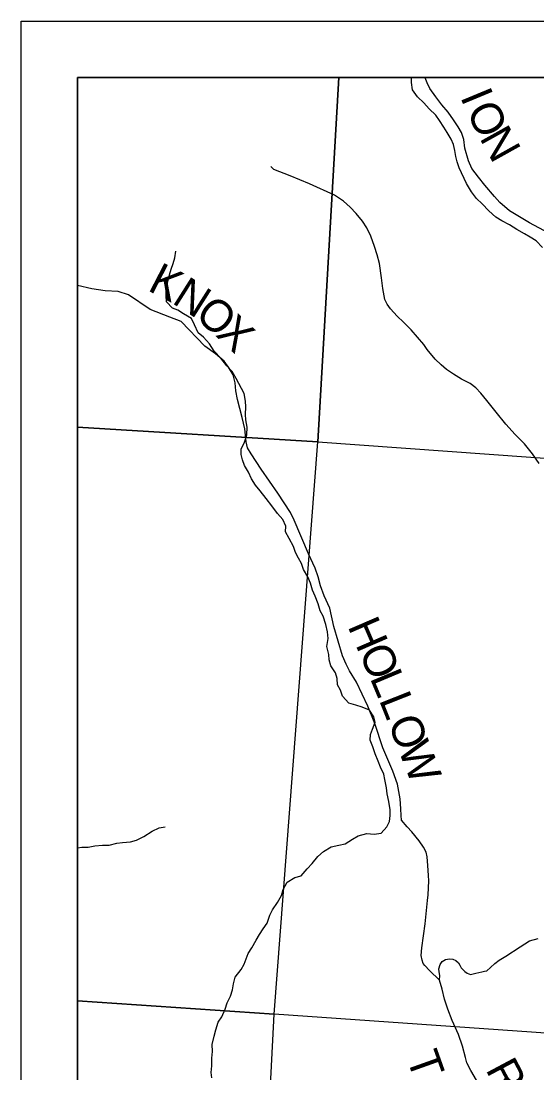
# Model space of a CAD drawing. Extents: x -13.7 to 34, y 0 to 32.3.
# Drawn here: x 23.417 to 24.332, y 19.134 to 21 of the extents above; entities that cross this region are included whole.
import ezdxf

# ---------------------------------------------------------------- set-up
doc = ezdxf.new("R2010")
doc.units = 0
for name, color, linetype in [('GM_X_Corporation', 7, 'Continuous'), ('GM_X_County_Road', 7, 'Continuous'), ('GM_X_County_Road_Text', 7, 'Continuous'), ('GM_X_Minor_River', 7, 'Continuous'), ('GM_X_Township_Road', 7, 'Continuous'), ('GM_X_Township_Road_Text', 7, 'Continuous'), ('SH_Data', 7, 'Continuous')]:
    doc.layers.add(name, color=color, linetype=linetype)

msp = doc.modelspace()

# ---------------------------------------------------------------- linework, layer by layer
at = {"layer": 'GM_X_Corporation'}
for points in [[(26.0026, 20.9), (23.5167, 20.9), (23.5167, 14.1)], [(26.0026, 20.9), (23.5167, 20.9), (23.5167, 15.1495)]]:
    msp.add_lwpolyline(points, dxfattribs=at)
for points in [[(23.9809, 20.9), (23.5167, 20.9), (23.5167, 20.2798), (23.9438, 20.2537)], [(24.9905, 20.9), (23.9809, 20.9), (23.9438, 20.2537), (24.938, 20.1823)], [(23.5167, 20.2798), (23.5167, 19.2621), (23.8661, 19.2385), (23.9438, 20.2537)], [(23.9438, 20.2537), (24.938, 20.1823), (24.8727, 19.1684), (23.8661, 19.2385)], [(23.5167, 19.2621), (23.5167, 18.2375), (23.8099, 18.2197), (23.8254, 18.4657), (23.8456, 18.8482), (23.8661, 19.2385)]]:
    msp.add_lwpolyline(points, close=True, dxfattribs=at)
at = {"layer": 'GM_X_County_Road'}
msp.add_lwpolyline([(24.3534, 20.6236), (24.3191, 20.642), (24.2838, 20.6633), (24.2666, 20.678), (24.257, 20.6889), (24.2399, 20.709), (24.2284, 20.7232), (24.217, 20.7383), (24.211, 20.7519), (24.2046, 20.7746), (24.2026, 20.7901), (24.1983, 20.8021), (24.1928, 20.8126), (24.1846, 20.8246), (24.1747, 20.8384), (24.1636, 20.8513), (24.153, 20.8658), (24.1421, 20.8805), (24.1376, 20.8905), (24.1343, 20.8994), (24.1343, 20.9)], dxfattribs=at)
at = {"layer": 'GM_X_Minor_River'}
for points in [[(24.3425, 20.5983), (24.3311, 20.6104), (24.3205, 20.6169), (24.3106, 20.6229), (24.2966, 20.6305), (24.2837, 20.6384), (24.2704, 20.6456), (24.2594, 20.6524), (24.2473, 20.6634), (24.2352, 20.6759), (24.2249, 20.6854), (24.2162, 20.6971), (24.2071, 20.7119), (24.1942, 20.7399), (24.1908, 20.7501), (24.1885, 20.76), (24.1866, 20.7702), (24.1843, 20.7808), (24.1801, 20.7903), (24.1733, 20.8021), (24.1672, 20.8115), (24.1592, 20.8236), (24.1532, 20.8331), (24.1414, 20.8445), (24.1316, 20.8547), (24.1206, 20.8657), (24.1118, 20.8778), (24.1099, 20.8911), (24.1095, 20.9)], [(24.0412, 19.7127), (24.0363, 19.7248), (24.037, 19.7347), (24.0404, 19.7442), (24.045, 19.7567), (24.0427, 19.7662), (24.0355, 19.7779), (24.0222, 19.7832), (24.0112, 19.7866), (23.9987, 19.7904), (23.9873, 19.8029), (23.9835, 19.8131), (23.9786, 19.8229), (23.9778, 19.8339), (23.9748, 19.8438), (23.9664, 19.8567), (23.9634, 19.8669), (23.963, 19.8768), (23.9592, 19.8908), (23.9618, 19.9048), (23.9607, 19.9169), (23.958, 19.9298), (23.9527, 19.9446), (23.9474, 19.9541), (23.944, 19.9666), (23.9386, 19.9802), (23.9341, 19.9908), (23.9307, 20.0033), (23.9257, 20.0143), (23.9181, 20.0272), (23.9143, 20.0378), (23.909, 20.0476), (23.9041, 20.0575), (23.9003, 20.0681), (23.8927, 20.0821), (23.8862, 20.0942), (23.8866, 20.1041), (23.8813, 20.1158), (23.8718, 20.1264), (23.8616, 20.1401), (23.8517, 20.1533), (23.8411, 20.1669), (23.8327, 20.1768), (23.8259, 20.1882), (23.8206, 20.1999), (23.8134, 20.212), (23.8096, 20.2215), (23.8073, 20.2313), (23.8073, 20.2408), (23.8133, 20.2533), (23.8175, 20.2662), (23.8178, 20.2795), (23.8155, 20.2928), (23.8152, 20.3022), (23.8159, 20.3155), (23.8151, 20.3257), (23.8125, 20.3394), (23.7988, 20.3659), (23.7912, 20.3784), (23.7821, 20.3886), (23.7711, 20.4019), (23.7597, 20.4144), (23.7514, 20.4276), (23.7408, 20.4394), (23.7313, 20.4469), (23.7244, 20.461), (23.7191, 20.4727), (23.7051, 20.4806), (23.6952, 20.4875), (23.6858, 20.4908), (23.6751, 20.5022), (23.6744, 20.5124), (23.6744, 20.5219), (23.6766, 20.5352), (23.6804, 20.5496), (23.683, 20.5602), (23.6868, 20.5701), (23.6894, 20.5799), (23.6917, 20.5921)], [(23.7552, 19.1255), (23.7544, 19.135), (23.7552, 19.1471), (23.7555, 19.1607), (23.7563, 19.1725), (23.7562, 19.1846), (23.7596, 19.1998), (23.7623, 19.2108), (23.7664, 19.2244), (23.7729, 19.2339), (23.7789, 19.2476), (23.7827, 19.2586), (23.7887, 19.2707), (23.7921, 19.2817), (23.794, 19.2927), (23.7966, 19.3041), (23.8072, 19.3178), (23.8129, 19.3273), (23.8163, 19.3367), (23.8201, 19.3462), (23.8261, 19.3561), (23.8341, 19.3701), (23.8397, 19.38), (23.8465, 19.3902), (23.8533, 19.4001), (23.8586, 19.4141), (23.8632, 19.4236), (23.8719, 19.4365), (23.879, 19.4494), (23.8817, 19.4597), (23.8889, 19.4726), (23.9029, 19.4809), (23.9142, 19.484), (23.9244, 19.4965), (23.9335, 19.506), (23.9437, 19.5181), (23.9536, 19.5272), (23.9672, 19.5352), (23.9808, 19.5386), (23.9918, 19.5409), (24.0051, 19.5493), (24.0153, 19.555), (24.0304, 19.5588), (24.0437, 19.5581), (24.0558, 19.5596), (24.066, 19.571), (24.0706, 19.5805), (24.0721, 19.5911), (24.0717, 19.6013), (24.0694, 19.6157), (24.0667, 19.6294), (24.0652, 19.6403), (24.0625, 19.6548), (24.0606, 19.6642), (24.0545, 19.6767), (24.0504, 19.6873), (24.0454, 19.7006), (24.0412, 19.7127)], [(23.5167, 19.5337), (23.5244, 19.5346), (23.5361, 19.5346), (23.5479, 19.5373), (23.5611, 19.5384), (23.5729, 19.5385), (23.5869, 19.5419), (23.5967, 19.5434), (23.6107, 19.5446), (23.6217, 19.5472), (23.6346, 19.5537), (23.6497, 19.5632), (23.6618, 19.5693), (23.6728, 19.5708)]]:
    msp.add_lwpolyline(points, dxfattribs=at)
at = {"layer": 'GM_X_Township_Road'}
for points in [[(24.3363, 20.215), (24.3245, 20.2327), (24.3106, 20.2499), (24.294, 20.267), (24.2771, 20.2852), (24.2599, 20.3061), (24.2433, 20.3268), (24.2326, 20.3399), (24.2237, 20.3497), (24.2137, 20.3569), (24.1988, 20.3651), (24.1843, 20.374), (24.1721, 20.3822), (24.1623, 20.39), (24.1519, 20.4002), (24.1374, 20.4176), (24.1316, 20.4265), (24.1092, 20.4521), (24.0954, 20.4658), (24.0845, 20.4765), (24.0724, 20.4897), (24.0667, 20.4977), (24.0627, 20.5061), (24.0591, 20.5257), (24.0566, 20.5444), (24.0527, 20.5699), (24.0489, 20.5855), (24.0442, 20.6004), (24.0377, 20.6186), (24.0304, 20.6335), (24.0226, 20.6453), (24.0117, 20.6584), (24.001, 20.6698), (23.9892, 20.6803), (23.9732, 20.6911), (23.9285, 20.711), (23.8943, 20.7252), (23.8654, 20.7367), (23.86, 20.7419)], [(24.2249, 19.1219), (24.2151, 19.1386), (24.2079, 19.1526), (24.2059, 19.162), (24.2005, 19.182), (24.1933, 19.2026), (24.1818, 19.2277), (24.174, 19.2473), (24.1683, 19.2653), (24.1642, 19.2833), (24.1595, 19.299), (24.1416, 19.3159), (24.1334, 19.325), (24.1304, 19.3288), (24.1285, 19.3345), (24.127, 19.3428), (24.1279, 19.3565), (24.1343, 19.3988), (24.1381, 19.4403), (24.1393, 19.4506), (24.1403, 19.4754), (24.1401, 19.4848), (24.139, 19.5023), (24.1376, 19.518), (24.1359, 19.5258), (24.131, 19.535), (24.1235, 19.5461), (24.1103, 19.5623), (24.1021, 19.5712), (24.0922, 19.5827), (24.0912, 19.5913), (24.091, 19.6028), (24.0895, 19.6205), (24.0851, 19.6465), (24.0768, 19.6697), (24.0589, 19.7113), (24.0446, 19.7542), (24.0325, 19.7852), (24.0123, 19.8275), (23.9997, 19.8477), (23.9939, 19.8593), (23.9875, 19.8744), (23.9722, 19.9262), (23.9648, 19.9589), (23.9548, 19.9803), (23.9481, 19.9984), (23.9443, 20.014), (23.9386, 20.0298), (23.9267, 20.055), (23.9014, 20.1149), (23.8947, 20.1282), (23.8723, 20.1624), (23.8432, 20.2051), (23.8252, 20.2325), (23.8187, 20.2431), (23.8162, 20.254), (23.8138, 20.2767), (23.809, 20.2968), (23.8007, 20.3289), (23.7981, 20.3443), (23.797, 20.3581), (23.793, 20.3726), (23.7852, 20.3862), (23.7775, 20.3965), (23.7616, 20.4097), (23.7431, 20.4234), (23.7007, 20.4669), (23.681, 20.4749), (23.6461, 20.4886), (23.6072, 20.5143), (23.5891, 20.5204), (23.5658, 20.5214), (23.5426, 20.5249), (23.5167, 20.5312)], [(24.1595, 19.299), (24.1602, 19.3074), (24.1591, 19.3135), (24.1582, 19.3192), (24.1609, 19.3265), (24.1641, 19.3319), (24.1703, 19.3355), (24.1771, 19.3369), (24.1829, 19.3365), (24.1887, 19.3338), (24.1931, 19.3295), (24.1956, 19.3253), (24.1981, 19.3209), (24.2009, 19.3177), (24.2045, 19.3143), (24.2086, 19.3111), (24.2143, 19.3092), (24.2194, 19.3101), (24.2238, 19.3112), (24.2293, 19.3126), (24.2348, 19.3138), (24.2394, 19.3148), (24.2435, 19.3155), (24.25, 19.3214), (24.2578, 19.3285), (24.2653, 19.3346), (24.277, 19.3416), (24.3028, 19.358), (24.3192, 19.3688), (24.3344, 19.3731)]]:
    msp.add_lwpolyline(points, dxfattribs=at)
at = {"layer": 'SH_Data'}
for points in [[(23.4167, 21), (30.4167, 21), (30.4167, 14), (23.4167, 14)], [(23.5167, 20.9), (30.3167, 20.9), (30.3167, 14.1), (23.5167, 14.1)]]:
    msp.add_lwpolyline(points, close=True, dxfattribs=at)

# ---------------------------------------------------------------- texts
at = {"layer": 'GM_X_County_Road_Text'}
for s, rotation, p in [('I', 292.5335, (24.1957, 20.8658)), ('O', 295.873, (24.2062, 20.8409)), ('N', 299.1158, (24.2296, 20.7928))]:
    msp.add_text(s, height=0.0568, rotation=rotation, dxfattribs=at).set_placement(p)
at = {"layer": 'GM_X_Township_Road_Text'}
for s, rotation, p in [('K', 332.6432, (23.6395, 20.5231)), ('N', 327.5567, (23.6828, 20.5008)), ('O', 318.6962, (23.7231, 20.4754)), ('X', 316.7157, (23.7603, 20.4427)), ('H', 293.3263, (23.9958, 19.927)), ('O', 293.31, (24.0156, 19.8811)), ('L', 292.7118, (24.0353, 19.8353)), ('L', 291.5754, (24.0516, 19.7964)), ('O', 290.834, (24.0671, 19.7571)), ('W', 291.34, (24.0851, 19.7098)), ('T', 289.606, (24.1003, 19.162)), ('R', 298.0629, (24.2405, 19.1408))]:
    msp.add_text(s, height=0.0568, rotation=rotation, dxfattribs=at).set_placement(p)

doc.saveas('drawing.dxf')
